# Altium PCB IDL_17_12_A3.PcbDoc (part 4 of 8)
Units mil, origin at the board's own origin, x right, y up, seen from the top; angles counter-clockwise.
Board outline 5119.97 x 10350 mil, 6 copper layers (Top Signal, 3.3 Volt, GND, 5 Volt, Split Plane, Bot Signal), stack 66.2 mil thick; 510 components, 178 nets, 2317 pads, 385 vias.
Unrouted connection lines stored in the file: 1.
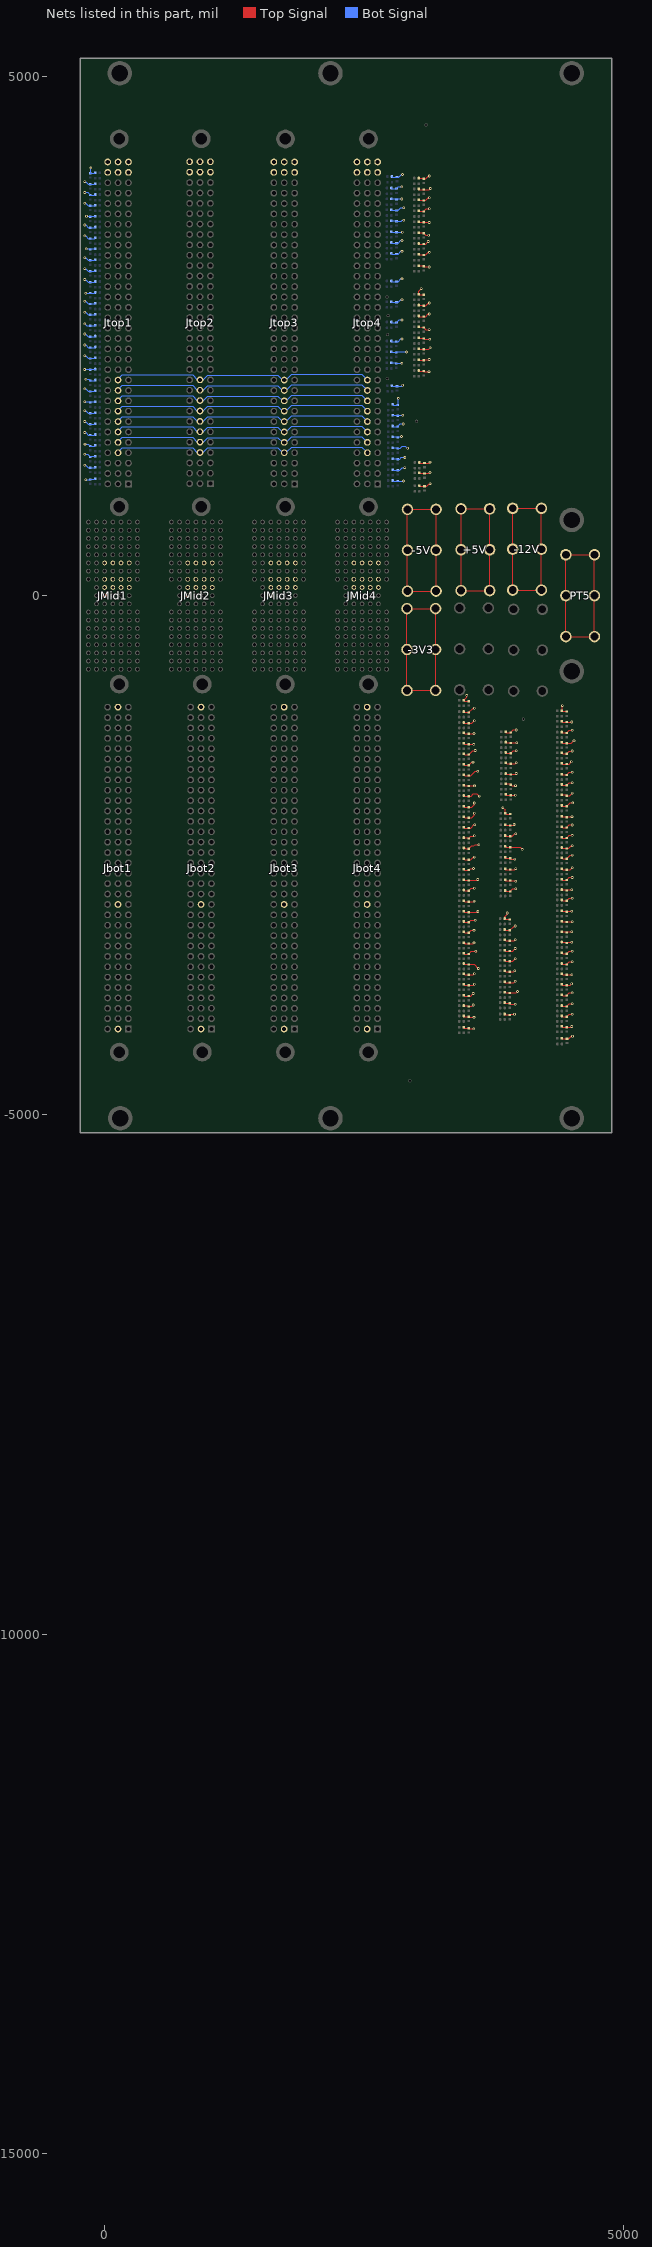
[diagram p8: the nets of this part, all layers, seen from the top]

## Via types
v1: diameter 25.59, hole 11.81, Top Signal to Bot Signal, 385 vias

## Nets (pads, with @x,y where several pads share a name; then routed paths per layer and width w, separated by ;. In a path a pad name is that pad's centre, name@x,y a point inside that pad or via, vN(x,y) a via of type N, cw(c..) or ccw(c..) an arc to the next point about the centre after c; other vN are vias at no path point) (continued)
5V: +5V.1 +5V.2 +5V.3 +5V.4 +5V.5 +5V.6 CR_IDL_17_12_TerA1.2 CR_IDL_17_12_TerA2.2 CR_IDL_17_12_TerA3.2 CR_IDL_17_12_TerA4.2 CR_IDL_17_12_TerA5.2 CR_IDL_17_12_TerA6.2 CR_IDL_17_12_TerA7.2 CR_IDL_17_12_TerA8.2 CR_IDL_17_12_TerA9.2 CR_IDL_17_12_TerA10.2 CR_IDL_17_12_TerA11.2 CR_IDL_17_12_TerA12.2 CR_IDL_17_12_TerA13.2 CR_IDL_17_12_TerA14.2 CR_IDL_17_12_TerA15.2 CR_IDL_17_12_TerA16.2 CR_IDL_17_12_TerA17.2 CR_IDL_17_12_TerA18.2 CR_IDL_17_12_TerA19.2 CR_IDL_17_12_TerA20.2 CR_IDL_17_12_TerA21.2 CR_IDL_17_12_TerA22.2 CR_IDL_17_12_TerA23.2 CR_IDL_17_12_TerA24.2 CR_IDL_17_12_TerA25.2 CR_IDL_17_12_TerA26.2 CR_IDL_17_12_TerA27.2 CR_IDL_17_12_TerA28.2 CR_IDL_17_12_TerA29.2 CR_IDL_17_12_TerA30.2 CR_IDL_17_12_TerA31.2 CR_IDL_17_12_TerA32.2 CR_IDL_17_12_TerA33.2 CR_IDL_17_12_TerA34.2 CR_IDL_17_12_TerA35.2 CR_IDL_17_12_TerA36.2 CR_IDL_17_12_TerA37.2 CR_IDL_17_12_TerA38.2 CR_IDL_17_12_TerA39.2 CR_IDL_17_12_TerA40.2 CR_IDL_17_12_TerA41.2 CR_IDL_17_12_TerA42.2 CR_IDL_17_12_TerA43.2 CR_IDL_17_12_TerA44.2 CR_IDL_17_12_TerA45.2 CR_IDL_17_12_TerA46.2 CR_IDL_17_12_TerA47.2 CR_IDL_17_12_TerA48.2 CR_IDL_17_12_TerA49.2 CR_IDL_17_12_TerA50.2 CR_IDL_17_12_TerA51.2 CR_IDL_17_12_TerA52.2 CR_IDL_17_12_TerA53.2 CR_IDL_17_12_TerA54.2 CR_IDL_17_12_TerA55.2 CR_IDL_17_12_TerA56.2 CR_IDL_17_12_TerA57.2 CR_IDL_17_12_TerA58.2 CR_IDL_17_12_TerA59.2 CR_IDL_17_12_TerA60.2 CR_IDL_17_12_TerA61.2 CR_IDL_17_12_TerA62.2 CR_IDL_17_12_TerA63.2 CR_IDL_17_12_TerA64.2 CR_IDL_17_12_TerA65.2 CR_IDL_17_12_TerA66.2 CR_IDL_17_12_TerA67.2 CR_IDL_17_12_TerA68.2 CR_IDL_17_12_TerA69.2 CR_IDL_17_12_TerA70.2 CR_IDL_17_12_TerA71.2 CR_IDL_17_12_TerA72.2 CRB_IDL_17_12_TerB1.2 CRB_IDL_17_12_TerB2.2 CRB_IDL_17_12_TerB3.2 CRB_IDL_17_12_TerB4.2 CRB_IDL_17_12_TerB5.2 CRB_IDL_17_12_TerB6.2 CRB_IDL_17_12_TerB7.2 CRB_IDL_17_12_TerB8.2 CRB_IDL_17_12_TerB9.2 CRB_IDL_17_12_TerB10.2 CRB_IDL_17_12_TerB11.2 CRB_IDL_17_12_TerB12.2 CRB_IDL_17_12_TerB13.2 CRB_IDL_17_12_TerB14.2 CRB_IDL_17_12_TerB15.2 CRB_IDL_17_12_TerB16.2 CRB_IDL_17_12_TerB17.2 CRB_IDL_17_12_TerB18.2 CRB_IDL_17_12_TerB19.2 CRB_IDL_17_12_TerB20.2 CRB_IDL_17_12_TerB21.2 CRB_IDL_17_12_TerB22.2 CRB_IDL_17_12_TerB23.2 CRB_IDL_17_12_TerB24.2 CRB_IDL_17_12_TerB25.2 CRB_IDL_17_12_TerB26.2 CRB_IDL_17_12_TerB27.2 CRB_IDL_17_12_TerB28.2 CRB_IDL_17_12_TerB29.2 CRB_IDL_17_12_TerB30.2 CRB_IDL_17_12_TerB31.2 CRB_IDL_17_12_TerB32.2 CRB_IDL_17_12_TerB33.2 CRB_IDL_17_12_TerB34.2 CRB_IDL_17_12_TerB35.2 CRB_IDL_17_12_TerB36.2 CRB_IDL_17_12_TerB37.2 CRB_IDL_17_12_TerB38.2 CRB_IDL_17_12_TerB39.2 CRB_IDL_17_12_TerB40.2 CRB_IDL_17_12_TerB41.2 CRB_IDL_17_12_TerB42.2 CRB_IDL_17_12_TerB43.2 CRB_IDL_17_12_TerB44.2 CRB_IDL_17_12_TerB45.2 CRB_IDL_17_12_TerB46.2 CRB_IDL_17_12_TerB47.2 CRB_IDL_17_12_TerB48.2 CRB_IDL_17_12_TerB49.2 CRB_IDL_17_12_TerB50.2 CRB_IDL_17_12_TerB51.2 CRB_IDL_17_12_TerB52.2 CRB_IDL_17_12_TerB53.2 CRB_IDL_17_12_TerB54.2 CRB_IDL_17_12_TerB55.2 CRB_IDL_17_12_TerB56.2 CRB_IDL_17_12_TerB57.2 CRB_IDL_17_12_TerB58.2 CRB_IDL_17_12_TerB59.2 CRB_IDL_17_12_TerB60.2 CRB_IDL_17_12_TerB61.2 CRB_IDL_17_12_TerB62.2 CRB_IDL_17_12_TerB63.2 CRB_IDL_17_12_TerB64.2 CRB_IDL_17_12_TerB65.2 CRB_IDL_17_12_TerB66.2 CRB_IDL_17_12_TerB67.2 CRB_IDL_17_12_TerB68.2 CRB_IDL_17_12_TerB69.2 CRB_IDL_17_12_TerB70.2 CRB_IDL_17_12_TerB71.2 CRB_IDL_17_12_TerB72.2 CRB_IDL_17_12_TerB73.2 CRB_IDL_17_12_TerB74.2 CRB_IDL_17_12_TerB75.2 CRB_IDL_17_12_TerB76.2 CRB_IDL_17_12_TerB77.2 CRB_IDL_17_12_TerB78.2 CRB_IDL_17_12_TerB79.2 CRB_IDL_17_12_TerB80.2 CRB_IDL_17_12_TerB81.2 CRB_IDL_17_12_TerB82.2 CRB_IDL_17_12_TerB83.2 CRB_IDL_17_12_TerB84.2 CRB_IDL_17_12_TerB85.2 CRB_IDL_17_12_TerB86.2 CRB_IDL_17_12_TerB87.2 CRB_IDL_17_12_TerB88.2 CRB_IDL_17_12_TerB89.2 Jbot1.B1 Jbot1.B13 Jbot1.B32 Jbot2.B1 Jbot2.B13 Jbot2.B32 Jbot3.B1 Jbot3.B13 Jbot3.B32 Jbot4.B1 Jbot4.B13 Jbot4.B32 Jtop1.A32 Jtop1.B31 Jtop1.B32 Jtop1.C32 Jtop2.A32 Jtop2.B31 Jtop2.B32 Jtop2.C32 Jtop3.A32 Jtop3.B31 Jtop3.B32 Jtop3.C32 Jtop4.A32 Jtop4.B31 Jtop4.B32 Jtop4.C32 R1R_IDL_17_12_TerA1.2 R1R_IDL_17_12_TerA2.2 R1R_IDL_17_12_TerA3.2 R1R_IDL_17_12_TerA4.2 R1R_IDL_17_12_TerA5.2 R1R_IDL_17_12_TerA6.2 R1R_IDL_17_12_TerA7.2 R1R_IDL_17_12_TerA8.2 R1R_IDL_17_12_TerA9.2 R1R_IDL_17_12_TerA10.2 R1R_IDL_17_12_TerA11.2 R1R_IDL_17_12_TerA12.2 R1R_IDL_17_12_TerA13.2 R1R_IDL_17_12_TerA14.2 R1R_IDL_17_12_TerA15.2 R1R_IDL_17_12_TerA16.2 R1R_IDL_17_12_TerA17.2 R1R_IDL_17_12_TerA18.2 R1R_IDL_17_12_TerA19.2 R1R_IDL_17_12_TerA20.2 R1R_IDL_17_12_TerA21.2 R1R_IDL_17_12_TerA22.2 R1R_IDL_17_12_TerA23.2 R1R_IDL_17_12_TerA24.2 R1R_IDL_17_12_TerA25.2 R1R_IDL_17_12_TerA26.2 R1R_IDL_17_12_TerA27.2 R1R_IDL_17_12_TerA28.2 R1R_IDL_17_12_TerA29.2 R1R_IDL_17_12_TerA30.2 R1R_IDL_17_12_TerA31.2 R1R_IDL_17_12_TerA32.2 R1R_IDL_17_12_TerA33.2 R1R_IDL_17_12_TerA34.2 R1R_IDL_17_12_TerA35.2 R1R_IDL_17_12_TerA36.2 R1R_IDL_17_12_TerA37.2 R1R_IDL_17_12_TerA38.2 R1R_IDL_17_12_TerA39.2 R1R_IDL_17_12_TerA40.2 R1R_IDL_17_12_TerA41.2 R1R_IDL_17_12_TerA42.2 R1R_IDL_17_12_TerA43.2 R1R_IDL_17_12_TerA44.2 R1R_IDL_17_12_TerA45.2 R1R_IDL_17_12_TerA46.2 R1R_IDL_17_12_TerA47.2 R1R_IDL_17_12_TerA48.2 R1R_IDL_17_12_TerA49.2 R1R_IDL_17_12_TerA50.2 R1R_IDL_17_12_TerA51.2 R1R_IDL_17_12_TerA52.2 R1R_IDL_17_12_TerA53.2 R1R_IDL_17_12_TerA54.2 R1R_IDL_17_12_TerA55.2 R1R_IDL_17_12_TerA56.2 R1R_IDL_17_12_TerA57.2 R1R_IDL_17_12_TerA58.2 R1R_IDL_17_12_TerA59.2 R1R_IDL_17_12_TerA60.2 R1R_IDL_17_12_TerA61.2 R1R_IDL_17_12_TerA62.2 R1R_IDL_17_12_TerA63.2 R1R_IDL_17_12_TerA64.2 R1R_IDL_17_12_TerA65.2 R1R_IDL_17_12_TerA66.2 R1R_IDL_17_12_TerA67.2 R1R_IDL_17_12_TerA68.2 R1R_IDL_17_12_TerA69.2 R1R_IDL_17_12_TerA70.2 R1R_IDL_17_12_TerA71.2 R1R_IDL_17_12_TerA72.2 R1RB_IDL_17_12_TerB1.2 R1RB_IDL_17_12_TerB2.2 R1RB_IDL_17_12_TerB3.2 R1RB_IDL_17_12_TerB4.2 R1RB_IDL_17_12_TerB5.2 R1RB_IDL_17_12_TerB6.2 R1RB_IDL_17_12_TerB7.2 R1RB_IDL_17_12_TerB8.2 R1RB_IDL_17_12_TerB9.2 R1RB_IDL_17_12_TerB10.2 R1RB_IDL_17_12_TerB11.2 R1RB_IDL_17_12_TerB12.2 R1RB_IDL_17_12_TerB13.2 R1RB_IDL_17_12_TerB14.2 R1RB_IDL_17_12_TerB15.2 R1RB_IDL_17_12_TerB16.2 R1RB_IDL_17_12_TerB17.2 R1RB_IDL_17_12_TerB18.2 R1RB_IDL_17_12_TerB19.2 R1RB_IDL_17_12_TerB20.2 R1RB_IDL_17_12_TerB21.2 R1RB_IDL_17_12_TerB22.2 R1RB_IDL_17_12_TerB23.2 R1RB_IDL_17_12_TerB24.2 R1RB_IDL_17_12_TerB25.2 R1RB_IDL_17_12_TerB26.2 R1RB_IDL_17_12_TerB27.2 R1RB_IDL_17_12_TerB28.2 R1RB_IDL_17_12_TerB29.2 R1RB_IDL_17_12_TerB30.2 R1RB_IDL_17_12_TerB31.2 R1RB_IDL_17_12_TerB32.2 R1RB_IDL_17_12_TerB33.2 R1RB_IDL_17_12_TerB34.2 R1RB_IDL_17_12_TerB35.2 R1RB_IDL_17_12_TerB36.2 R1RB_IDL_17_12_TerB37.2 R1RB_IDL_17_12_TerB38.2 R1RB_IDL_17_12_TerB39.2 R1RB_IDL_17_12_TerB40.2 R1RB_IDL_17_12_TerB41.2 R1RB_IDL_17_12_TerB42.2 R1RB_IDL_17_12_TerB43.2 R1RB_IDL_17_12_TerB44.2 R1RB_IDL_17_12_TerB45.2 R1RB_IDL_17_12_TerB46.2 R1RB_IDL_17_12_TerB47.2 R1RB_IDL_17_12_TerB48.2 R1RB_IDL_17_12_TerB49.2 R1RB_IDL_17_12_TerB50.2 R1RB_IDL_17_12_TerB51.2 R1RB_IDL_17_12_TerB52.2 R1RB_IDL_17_12_TerB53.2 R1RB_IDL_17_12_TerB54.2 R1RB_IDL_17_12_TerB55.2 R1RB_IDL_17_12_TerB56.2 R1RB_IDL_17_12_TerB57.2 R1RB_IDL_17_12_TerB58.2 R1RB_IDL_17_12_TerB59.2 R1RB_IDL_17_12_TerB60.2 R1RB_IDL_17_12_TerB61.2 R1RB_IDL_17_12_TerB62.2 R1RB_IDL_17_12_TerB63.2 R1RB_IDL_17_12_TerB64.2 R1RB_IDL_17_12_TerB65.2 R1RB_IDL_17_12_TerB66.2 R1RB_IDL_17_12_TerB67.2 R1RB_IDL_17_12_TerB68.2 R1RB_IDL_17_12_TerB69.2 R1RB_IDL_17_12_TerB70.2 R1RB_IDL_17_12_TerB71.2 R1RB_IDL_17_12_TerB72.2 R1RB_IDL_17_12_TerB73.2 R1RB_IDL_17_12_TerB74.2 R1RB_IDL_17_12_TerB75.2 R1RB_IDL_17_12_TerB76.2 R1RB_IDL_17_12_TerB77.2 R1RB_IDL_17_12_TerB78.2 R1RB_IDL_17_12_TerB79.2 R1RB_IDL_17_12_TerB80.2 R1RB_IDL_17_12_TerB81.2 R1RB_IDL_17_12_TerB82.2 R1RB_IDL_17_12_TerB83.2 R1RB_IDL_17_12_TerB84.2 R1RB_IDL_17_12_TerB85.2 R1RB_IDL_17_12_TerB86.2 R1RB_IDL_17_12_TerB87.2 R1RB_IDL_17_12_TerB88.2 R1RB_IDL_17_12_TerB89.2 | length 18453.1
  Top Signal w8: Jtop4.A32@2628.72,4176.52 Jtop4.A32@2628.72,4182.06 ; R1R_IDL_17_12_TerA40.2@3024.42,2168.36 3030.32,2162.46 CR_IDL_17_12_TerA40.2@3073.37,2162.46 ; R1R_IDL_17_12_TerA39.2@3024.42,2273.36 3030.32,2267.46 CR_IDL_17_12_TerA39.2@3073.37,2267.46 3079.93,2274.01 v1(3124.74,2274.01) ; R1R_IDL_17_12_TerA38.2@3024.42,2378.36 3030.32,2372.46 CR_IDL_17_12_TerA38.2@3073.37,2372.46 3120.11,2372.46 v1(3133.9,2386.25) ; R1R_IDL_17_12_TerA37.2@3024.42,2483.36 3030.32,2477.46 CR_IDL_17_12_TerA37.2@3073.37,2477.46 3081.48,2469.35 v1(3130.24,2469.35) ; R1R_IDL_17_12_TerA36.2@3024.42,2588.36 3052.71,2582.46 CR_IDL_17_12_TerA36.2@3073.37,2582.46 3093.89,2561.94 v1(3124.64,2561.94) ; R1R_IDL_17_12_TerA35.2@3024.42,2693.36 3030.32,2687.46 CR_IDL_17_12_TerA35.2@3073.37,2687.46 3091.71,2687.46 3117.04,2712.79 v1(3126.89,2712.79) ; R1R_IDL_17_12_TerA34.2@3024.42,2798.36 3067.47,2798.36 CR_IDL_17_12_TerA34.2@3073.37,2792.46 3091.71,2792.46 3117.04,2817.79 v1(3126.89,2817.79) ; R1R_IDL_17_12_TerA32.2@3024.42,3178.36 3067.47,3178.36 CR_IDL_17_12_TerA32.2@3073.37,3172.46 3080.79,3165.04 v1(3125.26,3165.04) ; R1R_IDL_17_12_TerA31.2@3024.42,3286.36 3030.32,3280.46 CR_IDL_17_12_TerA31.2@3073.37,3280.46 3091.71,3280.46 3117.04,3305.79 v1(3126.89,3305.79) ; R1R_IDL_17_12_TerA30.2@3024.42,3391.36 3030.32,3385.46 CR_IDL_17_12_TerA30.2@3073.37,3385.46 3091.71,3385.46 v1(3117.04,3410.79) ; R1R_IDL_17_12_TerA29.2@3024.42,3496.36 3067.47,3496.36 CR_IDL_17_12_TerA29.2@3073.37,3490.46 3093.56,3470.27 v1(3119.45,3470.27) ; R1R_IDL_17_12_TerA28.2@3024.42,3601.36 3030.32,3595.46 CR_IDL_17_12_TerA28.2@3073.37,3595.46 3123.44,3595.46 v1(3126.01,3592.88) ; R1R_IDL_17_12_TerA27.2@3024.42,3706.36 3030.32,3700.46 CR_IDL_17_12_TerA27.2@3073.37,3700.46 3098.7,3725.79 v1(3126.89,3725.79) ; R1R_IDL_17_12_TerA26.2@3024.42,3811.36 3030.32,3805.46 CR_IDL_17_12_TerA26.2@3073.37,3805.46 3091.71,3805.46 3117.04,3830.79 v1(3126.89,3830.79) ; R1R_IDL_17_12_TerA25.2@3024.42,3916.36 3030.32,3910.46 CR_IDL_17_12_TerA25.2@3073.37,3910.46 CR_IDL_17_12_TerA25.2@3074.84,3910.46 ; R1R_IDL_17_12_TerA24.2@3024.42,4021.36 3067.47,4021.36 CR_IDL_17_12_TerA24.2@3073.37,4015.46 3091.71,4015.46 3117.04,4040.79 v1(3126.89,4040.79) ; R1R_IDL_17_12_TerA43.2@3030.24,1053.96 CR_IDL_17_12_TerA43.2@3079.2,1053.96 3100.74,1053.96 3125.86,1079.08 v1(3133.78,1079.08) ; R1R_IDL_17_12_TerA42.2@3030.32,1182.84 3036.22,1176.93 CR_IDL_17_12_TerA42.2@3079.27,1176.93 3123.46,1176.93 v1(3132.79,1186.26) ; R1R_IDL_17_12_TerA41.2@3030.32,1276.93 CR_IDL_17_12_TerA41.2@3079.27,1276.93 3123.46,1276.93 v1(3132.79,1286.26) ; v1(3048.76,2956.88) 3024.42,2932.54 R1R_IDL_17_12_TerA33.2@3024.42,2903.36 3030.32,2897.46 CR_IDL_17_12_TerA33.2@3073.37,2897.46 ; CR_IDL_17_12_TerA25.2@3073.11,3908.73 CR_IDL_17_12_TerA25.2@3074.84,3910.46 ; CR_IDL_17_12_TerA40.2@3073.37,2157.75 v1(3123.09,2157.75) ; v1(3136.58,3921.34) 3125.69,3910.46 CR_IDL_17_12_TerA25.2@3074.84,3910.46 ; R1RB_IDL_17_12_TerB31.2@3457.78,-4047.31 3457.78,-4055.81 CRB_IDL_17_12_TerB31.2@3506.6,-4055.81 3512.11,-4061.32 v1(3556.4,-4061.32) ; R1RB_IDL_17_12_TerB30.2@3457.78,-3947.31 3498.1,-3947.31 CRB_IDL_17_12_TerB30.2@3506.6,-3955.81 3535.75,-3955.81 v1(3549.99,-3941.58) ; R1RB_IDL_17_12_TerB29.2@3457.78,-3847.31 3466.29,-3855.81 CRB_IDL_17_12_TerB29.2@3506.6,-3855.81 3524.94,-3855.81 v1(3550.27,-3830.48) ; R1RB_IDL_17_12_TerB28.2@3457.78,-3742.31 3466.29,-3750.81 CRB_IDL_17_12_TerB28.2@3506.6,-3750.81 3550.79,-3750.81 v1(3560.12,-3741.48) ; R1RB_IDL_17_12_TerB27.2@3457.78,-3642.31 3466.29,-3650.81 CRB_IDL_17_12_TerB27.2@3506.6,-3650.81 3550.79,-3650.81 v1(3560.12,-3641.48) ; R1RB_IDL_17_12_TerB26.2@3457.78,-3542.31 3466.29,-3550.81 CRB_IDL_17_12_TerB26.2@3506.6,-3550.81 ; R1RB_IDL_17_12_TerB25.2@3457.78,-3442.31 3466.29,-3450.81 CRB_IDL_17_12_TerB25.2@3506.6,-3450.81 3532.34,-3425.08 v1(3574.01,-3425.08) 3579.11,-3425.08 3582.06,-3428.02 v1@3574.01,-3428.02 ; R1RB_IDL_17_12_TerB23.2@3457.78,-3237.31 3466.29,-3245.81 CRB_IDL_17_12_TerB23.2@3506.6,-3245.81 3529,-3223.41 v1(3557.19,-3223.41) ; R1RB_IDL_17_12_TerB22.2@3457.78,-3137.31 3466.29,-3145.81 CRB_IDL_17_12_TerB22.2@3506.6,-3145.81 3525.99,-3126.43 v1(3569.38,-3126.43) ; R1RB_IDL_17_12_TerB21.2@3457.78,-3039.31 3466.29,-3047.81 CRB_IDL_17_12_TerB21.2@3506.6,-3047.81 3588.51,-3047.81 v1(3594.38,-3041.94) ; R1RB_IDL_17_12_TerB20.2@3457.78,-2939.31 3466.29,-2947.81 CRB_IDL_17_12_TerB20.2@3506.6,-2947.81 3551.14,-2947.81 v1(3557.68,-2941.28) ; R1RB_IDL_17_12_TerB19.2@3457.78,-2834.31 3466.29,-2842.81 CRB_IDL_17_12_TerB19.2@3506.6,-2842.81 3531.93,-2817.48 v1(3560.12,-2817.48) ; R1RB_IDL_17_12_TerB18.2@3457.78,-2734.31 3466.29,-2742.81 CRB_IDL_17_12_TerB18.2@3506.6,-2742.81 3582.79,-2742.81 v1(3592.12,-2733.48) ; R1RB_IDL_17_12_TerB17.2@3457.78,-2634.31 3466.29,-2642.81 CRB_IDL_17_12_TerB17.2@3506.6,-2642.81 3521.78,-2627.63 v1(3551.65,-2627.63) ; R1RB_IDL_17_12_TerB16.2@3457.78,-2534.31 3466.29,-2542.81 CRB_IDL_17_12_TerB16.2@3506.6,-2542.81 3524.94,-2542.81 3550.27,-2517.48 v1(3560.12,-2517.48) ; R1RB_IDL_17_12_TerB15.2@3457.78,-2429.31 3469,-2429.31 3477.5,-2437.81 CRB_IDL_17_12_TerB15.2@3506.6,-2437.81 3534.91,-2409.51 3554.87,-2409.51 3566.41,-2397.97 v1(3603.72,-2397.97) ; R1RB_IDL_17_12_TerB14.2@3457.78,-2329.31 3498.1,-2329.31 CRB_IDL_17_12_TerB14.2@3506.6,-2337.81 3525.45,-2318.96 3553.64,-2318.96 v1(3560.12,-2312.48) ; R1RB_IDL_17_12_TerB13.2@3457.78,-2229.31 3466.29,-2237.81 CRB_IDL_17_12_TerB13.2@3506.6,-2237.81 3524.94,-2237.81 3560.12,-2202.63 3563.45,-2205.96 v1(3564.24,-2205.96) ; R1RB_IDL_17_12_TerB12.2@3457.78,-2129.31 3466.29,-2137.81 CRB_IDL_17_12_TerB12.2@3506.6,-2137.81 3534.79,-2137.81 3560.12,-2112.48 v1(3560.12,-2096.48) ; R1RB_IDL_17_12_TerB11.2@3457.78,-2029.31 3466.29,-2037.81 CRB_IDL_17_12_TerB11.2@3506.6,-2037.81 3534.79,-2037.81 3560.12,-2012.48 v1(3560.12,-1996.48) ; R1RB_IDL_17_12_TerB10.2@3457.78,-1924.31 3466.29,-1932.81 CRB_IDL_17_12_TerB10.2@3506.6,-1932.81 3527.88,-1932.81 3550.68,-1910.02 3583.33,-1910.02 v1@3606.12,-1932.81 ; R1RB_IDL_17_12_TerB9.2@3457.78,-1824.31 3466.29,-1832.81 CRB_IDL_17_12_TerB9.2@3506.6,-1832.81 3559.96,-1832.81 v1(3560.95,-1831.82) ; R1RB_IDL_17_12_TerB8.2@3457.78,-1724.31 3466.29,-1732.81 CRB_IDL_17_12_TerB8.2@3506.6,-1732.81 3527.31,-1732.81 3568.64,-1691.48 v1(3592.12,-1691.48) ; R1RB_IDL_17_12_TerB7.2@3457.78,-1624.31 3466.29,-1632.81 CRB_IDL_17_12_TerB7.2@3506.6,-1632.81 3536.29,-1603.13 v1(3546.97,-1603.13) ; R1RB_IDL_17_12_TerB6.2@3457.78,-1521.31 3466.29,-1529.81 CRB_IDL_17_12_TerB6.2@3506.6,-1529.81 3544.9,-1491.52 v1(3569.4,-1491.52) ; R1RB_IDL_17_12_TerB5.2@3457.78,-1421.31 3466.29,-1429.81 CRB_IDL_17_12_TerB5.2@3506.6,-1429.81 v1@3553.65,-1429.81 ; R1RB_IDL_17_12_TerB4.2@3457.78,-1321.31 3466.29,-1329.81 CRB_IDL_17_12_TerB4.2@3506.6,-1329.81 v1@3556.23,-1329.81 ; R1RB_IDL_17_12_TerB3.2@3457.78,-1221.31 3466.29,-1229.81 CRB_IDL_17_12_TerB3.2@3506.6,-1229.81 3534.79,-1229.81 v1(3560.12,-1204.48) ; R1RB_IDL_17_12_TerB2.2@3457.78,-1116.31 3466.29,-1124.81 CRB_IDL_17_12_TerB2.2@3506.6,-1124.81 3547.93,-1083.48 v1(3560.12,-1083.48) ; R1RB_IDL_17_12_TerB32.2@3457.87,-4164.87 CRB_IDL_17_12_TerB32.2@3506.2,-4164.87 3513.39,-4172.06 v1(3554.44,-4172.06) ; v1(3487.68,-960.63) 3486.47,-960.63 3486.47,-979.46 R1RB_IDL_17_12_TerB1.2@3457.09,-1008.84 3465.59,-1017.34 CRB_IDL_17_12_TerB1.2@3505.91,-1017.34 ; CRB_IDL_17_12_TerB26.2@3506.59,-3550.24 3514.6,-3550.08 3558.63,-3550.08 v1(3598.99,-3590.44) ; v1@3560.44,-3344.08 v1(3556.33,-3344.08) 3549.59,-3350.81 CRB_IDL_17_12_TerB24.2@3506.6,-3350.81 3477.5,-3350.81 ; v1(3835.08,-2041.02) 3856.73,-2062.68 R1RB_IDL_17_12_TerB40.2@3856.73,-2094.54 3865.24,-2103.05 CRB_IDL_17_12_TerB40.2@3905.55,-2103.05 ; R1RB_IDL_17_12_TerB57.2@3847.52,-4037.02 CRB_IDL_17_12_TerB57.2@3900.51,-4037.02 3907.21,-4030.33 v1(3946.67,-4030.33) ; R1RB_IDL_17_12_TerB56.2@3851.73,-3917.54 3851.73,-3926.05 CRB_IDL_17_12_TerB56.2@3900.55,-3926.05 3908.32,-3933.81 v1(3953.35,-3933.81) ; R1RB_IDL_17_12_TerB55.2@3851.73,-3817.54 3860.24,-3826.05 CRB_IDL_17_12_TerB55.2@3900.55,-3826.05 3961.69,-3826.05 v1(3975.74,-3812) ; R1RB_IDL_17_12_TerB54.2@3851.73,-3717.54 3851.73,-3726.05 CRB_IDL_17_12_TerB54.2@3900.55,-3726.05 3939.37,-3726.05 v1(3952.88,-3712.54) ; R1RB_IDL_17_12_TerB53.2@3851.73,-3612.54 3860.24,-3621.05 CRB_IDL_17_12_TerB53.2@3900.55,-3621.05 3939.18,-3621.05 ; R1RB_IDL_17_12_TerB52.2@3851.73,-3512.54 3860.24,-3521.05 CRB_IDL_17_12_TerB52.2@3900.55,-3521.05 3928.74,-3521.05 v1(3954.07,-3495.72) ; R1RB_IDL_17_12_TerB51.2@3851.73,-3414.54 3860.24,-3423.05 CRB_IDL_17_12_TerB51.2@3900.55,-3423.05 3928.74,-3423.05 v1(3954.07,-3397.72) ; R1RB_IDL_17_12_TerB50.2@3851.73,-3314.54 3860.24,-3323.05 CRB_IDL_17_12_TerB50.2@3900.55,-3323.05 3944.74,-3323.05 v1(3954.07,-3313.72) ; R1RB_IDL_17_12_TerB49.2@3852.45,-3223.05 CRB_IDL_17_12_TerB49.2@3900.55,-3223.05 3941.88,-3181.72 v1(3954.07,-3181.72) ; R1RB_IDL_17_12_TerB47.2@3854.98,-2848.05 CRB_IDL_17_12_TerB47.2@3905.55,-2848.05 3930.88,-2822.72 v1(3959.07,-2822.72) ; R1RB_IDL_17_12_TerB46.2@3856.66,-2743.05 CRB_IDL_17_12_TerB46.2@3905.55,-2743.05 3952.4,-2743.05 v1(3959.07,-2749.72) ; R1RB_IDL_17_12_TerB44.2@3856.73,-2519.54 3856.73,-2528.05 CRB_IDL_17_12_TerB44.2@3905.55,-2528.05 3914.52,-2537.01 v1(3948.08,-2537.01) ; R1RB_IDL_17_12_TerB43.2@3856.73,-2414.54 3865.24,-2423.05 CRB_IDL_17_12_TerB43.2@3905.55,-2423.05 4000.4,-2423.05 v1(4021.07,-2443.72) ; R1RB_IDL_17_12_TerB42.2@3856.73,-2309.54 3865.24,-2318.05 CRB_IDL_17_12_TerB42.2@3905.55,-2318.05 3923.89,-2318.05 3949.22,-2292.72 v1(3959.07,-2292.72) ; R1RB_IDL_17_12_TerB41.2@3856.76,-2213.05 CRB_IDL_17_12_TerB41.2@3905.55,-2213.05 3933.74,-2213.05 v1(3943.07,-2203.72) ; R1RB_IDL_17_12_TerB45.2@3858.06,-2638.05 CRB_IDL_17_12_TerB45.2@3905.55,-2638.05 3949.74,-2638.05 v1(3959.07,-2628.72) ; R1RB_IDL_17_12_TerB39.2@3861.73,-1912.89 3861.73,-1921.39 CRB_IDL_17_12_TerB39.2@3910.55,-1921.39 v1@3955.44,-1921.39 ; R1RB_IDL_17_12_TerB38.2@3861.73,-1812.89 3902.05,-1812.89 CRB_IDL_17_12_TerB38.2@3910.55,-1821.39 3918.34,-1829.18 v1(3955.89,-1829.18) ; R1RB_IDL_17_12_TerB37.2@3861.73,-1712.89 3870.24,-1721.39 CRB_IDL_17_12_TerB37.2@3910.55,-1721.39 3954.74,-1721.39 v1(3964.07,-1712.06) ; R1RB_IDL_17_12_TerB36.2@3861.73,-1609.89 3870.24,-1618.39 CRB_IDL_17_12_TerB36.2@3910.55,-1618.39 3953.59,-1618.39 v1(3962.92,-1609.06) ; R1RB_IDL_17_12_TerB35.2@3861.73,-1509.89 3870.24,-1518.39 CRB_IDL_17_12_TerB35.2@3910.55,-1518.39 3935.88,-1493.06 v1(3964.07,-1493.06) ; R1RB_IDL_17_12_TerB34.2@3861.73,-1409.89 3870.24,-1418.39 CRB_IDL_17_12_TerB34.2@3910.55,-1418.39 v1@3968.21,-1418.39 ; R1RB_IDL_17_12_TerB33.2@3863.95,-1318.39 CRB_IDL_17_12_TerB33.2@3910.55,-1318.39 3935.88,-1293.06 v1(3964.07,-1293.06) ; v1(3876.08,-3056.02) 3876.08,-3066.37 3851.73,-3090.71 R1RB_IDL_17_12_TerB48.2@3851.73,-3109.54 3860.24,-3118.05 CRB_IDL_17_12_TerB48.2@3900.55,-3118.05 ; R1RB_IDL_17_12_TerB88.2@4401.47,-4147.25 4409.97,-4155.75 CRB_IDL_17_12_TerB88.2@4450.29,-4155.75 4491.11,-4155.75 v1(4498.65,-4148.21) ; R1RB_IDL_17_12_TerB87.2@4401.47,-4047.25 4409.97,-4055.75 CRB_IDL_17_12_TerB87.2@4450.29,-4055.75 4475.62,-4030.42 v1(4503.81,-4030.42) ; R1RB_IDL_17_12_TerB86.2@4401.47,-3947.25 4409.97,-3955.75 CRB_IDL_17_12_TerB86.2@4450.29,-3955.75 4475.62,-3930.42 v1(4503.81,-3930.42) ; R1RB_IDL_17_12_TerB85.2@4401.47,-3842.25 4409.97,-3850.75 CRB_IDL_17_12_TerB85.2@4450.29,-3850.75 4475.62,-3825.42 v1(4503.81,-3825.42) ; R1RB_IDL_17_12_TerB84.2@4401.47,-3742.25 4409.97,-3750.75 CRB_IDL_17_12_TerB84.2@4450.29,-3750.75 4483.81,-3750.75 v1(4496.45,-3738.11) ; R1RB_IDL_17_12_TerB83.2@4401.47,-3642.25 4402.47,-3641.25 4411.39,-3650.17 v1(4499.28,-3650.17) ; R1RB_IDL_17_12_TerB82.2@4401.47,-3542.25 4409.97,-3550.75 CRB_IDL_17_12_TerB82.2@4450.29,-3550.75 4475.62,-3525.42 v1(4503.81,-3525.42) ; R1RB_IDL_17_12_TerB81.2@4401.47,-3440.25 4409.97,-3448.75 CRB_IDL_17_12_TerB81.2@4450.29,-3448.75 4475.62,-3423.42 v1(4503.81,-3423.42) ; R1RB_IDL_17_12_TerB80.2@4401.47,-3335.25 4404.19,-3337.97 v1(4498.45,-3337.97) ; R1RB_IDL_17_12_TerB79.2@4401.47,-3235.25 4402.54,-3236.32 v1(4497.78,-3236.32) ; R1RB_IDL_17_12_TerB78.2@4401.47,-3135.25 4406.56,-3140.34 CRB_IDL_17_12_TerB78.2@4450.29,-3140.34 ; R1RB_IDL_17_12_TerB77.2@4401.47,-3035.25 4404.48,-3038.27 v1(4498.52,-3038.27) ; R1RB_IDL_17_12_TerB76.2@4401.47,-2930.25 4409.97,-2938.75 CRB_IDL_17_12_TerB76.2@4450.29,-2938.75 4475.62,-2913.42 v1(4503.81,-2913.42) ; R1RB_IDL_17_12_TerB75.2@4401.47,-2830.25 4403.4,-2832.18 v1(4497.12,-2832.18) ; R1RB_IDL_17_12_TerB74.2@4401.47,-2730.25 4409.97,-2738.75 CRB_IDL_17_12_TerB74.2@4450.29,-2738.75 4475.62,-2713.42 v1(4503.81,-2713.42) ; R1RB_IDL_17_12_TerB73.2@4401.47,-2630.25 4409.97,-2638.75 CRB_IDL_17_12_TerB73.2@4450.29,-2638.75 4483.92,-2638.75 v1(4502.24,-2620.43) ; R1RB_IDL_17_12_TerB72.2@4401.47,-2525.25 4409.97,-2533.75 CRB_IDL_17_12_TerB72.2@4450.29,-2533.75 4485.47,-2498.56 v1(4503.81,-2498.56) ; R1RB_IDL_17_12_TerB71.2@4401.47,-2425.25 4409.97,-2433.75 CRB_IDL_17_12_TerB71.2@4450.29,-2433.75 4468.62,-2433.75 4493.95,-2408.42 v1(4503.81,-2408.42) ; R1RB_IDL_17_12_TerB70.2@4401.47,-2325.25 4409.97,-2333.75 CRB_IDL_17_12_TerB70.2@4450.29,-2333.75 4475.62,-2308.42 v1(4503.81,-2308.42) ; R1RB_IDL_17_12_TerB69.2@4401.47,-2225.25 4409.97,-2233.75 CRB_IDL_17_12_TerB69.2@4450.29,-2233.75 4475.62,-2208.42 v1(4503.81,-2208.42) ; R1RB_IDL_17_12_TerB68.2@4401.47,-2125.25 4403.97,-2127.76 CRB_IDL_17_12_TerB68.2@4450.29,-2127.76 ; R1RB_IDL_17_12_TerB67.2@4401.47,-2020.25 4409.97,-2028.75 CRB_IDL_17_12_TerB67.2@4450.29,-2028.75 4483.32,-1995.71 v1(4506.08,-1995.71) ; R1RB_IDL_17_12_TerB66.2@4401.47,-1918.25 4441.78,-1918.25 CRB_IDL_17_12_TerB66.2@4450.29,-1926.75 4478.48,-1926.75 v1(4503.81,-1901.42) ; R1RB_IDL_17_12_TerB65.2@4401.47,-1818.25 4409.97,-1826.75 CRB_IDL_17_12_TerB65.2@4450.29,-1826.75 4475.62,-1801.42 v1(4503.81,-1801.42) ; R1RB_IDL_17_12_TerB64.2@4401.47,-1718.25 4409.97,-1726.75 CRB_IDL_17_12_TerB64.2@4450.29,-1726.75 4475.62,-1701.42 v1(4503.81,-1701.42) ; R1RB_IDL_17_12_TerB63.2@4401.47,-1613.25 4409.97,-1621.75 CRB_IDL_17_12_TerB63.2@4450.29,-1621.75 4471.57,-1621.75 v1(4494.36,-1598.96) ; R1RB_IDL_17_12_TerB62.2@4401.47,-1513.25 4409.97,-1521.75 CRB_IDL_17_12_TerB62.2@4450.29,-1521.75 4475.62,-1496.42 v1(4503.81,-1496.42) ; R1RB_IDL_17_12_TerB61.2@4401.47,-1413.25 4409.97,-1421.75 CRB_IDL_17_12_TerB61.2@4450.29,-1421.75 4491.27,-1421.75 4516.6,-1396.42 v1(4519.81,-1396.42) ; R1RB_IDL_17_12_TerB60.2@4401.47,-1313.25 4409.97,-1321.75 CRB_IDL_17_12_TerB60.2@4450.29,-1321.75 4475.62,-1296.42 v1(4503.81,-1296.42) ; R1RB_IDL_17_12_TerB59.2@4401.47,-1208.25 4409.97,-1216.75 CRB_IDL_17_12_TerB59.2@4450.29,-1216.75 4498.05,-1216.75 v1(4498.56,-1217.26) ; R1RB_IDL_17_12_TerB58.2@4401.47,-1114.15 CRB_IDL_17_12_TerB58.2@4450.29,-1114.15 ; R1RB_IDL_17_12_TerB58.2@4401.47,-1108.25 4407.57,-1102.15 v1(4407.57,-1058.61) ; R1RB_IDL_17_12_TerB89.2@4403.41,-4262.25 4408.62,-4267.46 CRB_IDL_17_12_TerB89.2@4451.51,-4267.46 4469.85,-4267.46 4495.18,-4242.13 v1(4505.03,-4242.13) ; CRB_IDL_17_12_TerB78.2@4450.29,-3143.75 CRB_IDL_17_12_TerB78.2@4450.29,-3140.34 ; CRB_IDL_17_12_TerB68.2@4450.29,-2133.75 CRB_IDL_17_12_TerB68.2@4450.29,-2127.76 ; v1(4500.57,-2127.76) CRB_IDL_17_12_TerB68.2@4450.29,-2127.76 ; v1(4502.78,-3140.34) CRB_IDL_17_12_TerB78.2@4450.29,-3140.34 ; 3477.5,-3350.81 3466.29,-3350.81 R1RB_IDL_17_12_TerB24.2@3457.78,-3342.31 3469,-3342.31 3477.5,-3350.81
  Bot Signal w8: v1(-193.17,2178.31) -93.57,2178.31 R1R_IDL_17_12_TerA62.2@-89.92,2181.95 R1R_IDL_17_12_TerA62.2@-94.8,2181.95 ; v1(-192.4,1256.37) -182.55,1256.37 -157.22,1231.04 CR_IDL_17_12_TerA71.2@-138.88,1231.04 -95.83,1231.04 R1R_IDL_17_12_TerA71.2@-89.92,1236.95 ; v1(-192.4,1361.37) -164.21,1361.37 CR_IDL_17_12_TerA70.2@-138.88,1336.04 -132.97,1341.95 R1R_IDL_17_12_TerA70.2@-89.92,1341.95 ; v1(-192.4,1571.37) -182.55,1571.37 -157.22,1546.04 CR_IDL_17_12_TerA68.2@-138.88,1546.04 -95.83,1546.04 R1R_IDL_17_12_TerA68.2@-89.92,1551.95 ; v1(-192.4,1676.37) -182.55,1676.37 -157.22,1651.04 CR_IDL_17_12_TerA67.2@-138.88,1651.04 -95.83,1651.04 R1R_IDL_17_12_TerA67.2@-89.92,1656.95 ; v1(-192.4,1781.37) -182.55,1781.37 -157.22,1756.04 CR_IDL_17_12_TerA66.2@-138.88,1756.04 -95.83,1756.04 R1R_IDL_17_12_TerA66.2@-89.92,1761.95 ; v1(-192.4,1991.37) -182.55,1991.37 -157.22,1966.04 CR_IDL_17_12_TerA64.2@-138.88,1966.04 -95.83,1966.04 R1R_IDL_17_12_TerA64.2@-89.92,1971.95 ; v1(-192.4,2309.37) -182.55,2309.37 -157.22,2284.04 CR_IDL_17_12_TerA61.2@-138.88,2284.04 -95.83,2284.04 R1R_IDL_17_12_TerA61.2@-89.92,2289.95 ; v1(-192.4,2414.37) -182.55,2414.37 -157.22,2389.04 CR_IDL_17_12_TerA60.2@-138.88,2389.04 -95.83,2389.04 R1R_IDL_17_12_TerA60.2@-89.92,2394.95 ; v1(-192.4,2519.37) -182.55,2519.37 -157.22,2494.04 CR_IDL_17_12_TerA59.2@-138.88,2494.04 -95.83,2494.04 R1R_IDL_17_12_TerA59.2@-89.92,2499.95 ; v1(-192.4,2729.37) -182.55,2729.37 -157.22,2704.04 CR_IDL_17_12_TerA57.2@-138.88,2704.04 -95.83,2704.04 R1R_IDL_17_12_TerA57.2@-89.92,2709.95 ; v1(-192.4,2834.37) -182.55,2834.37 -157.22,2809.04 CR_IDL_17_12_TerA56.2@-138.88,2809.04 -95.83,2809.04 R1R_IDL_17_12_TerA56.2@-89.92,2814.95 ; v1(-192.4,3044.37) -182.55,3044.37 -157.22,3019.04 CR_IDL_17_12_TerA54.2@-138.88,3019.04 -95.83,3019.04 R1R_IDL_17_12_TerA54.2@-89.92,3024.95 ; v1(-192.4,3149.37) -182.55,3149.37 -157.22,3124.04 CR_IDL_17_12_TerA53.2@-138.88,3124.04 -95.83,3124.04 R1R_IDL_17_12_TerA53.2@-89.92,3129.95 ; v1(-192.4,3254.37) -182.55,3254.37 -157.22,3229.04 CR_IDL_17_12_TerA52.2@-138.88,3229.04 -95.83,3229.04 R1R_IDL_17_12_TerA52.2@-89.92,3234.95 ; v1(-192.4,3464.37) -182.55,3464.37 -157.22,3439.04 CR_IDL_17_12_TerA50.2@-138.88,3439.04 -95.83,3439.04 R1R_IDL_17_12_TerA50.2@-89.92,3444.95 ; v1(-192.4,3569.37) -182.55,3569.37 -157.22,3544.04 CR_IDL_17_12_TerA49.2@-138.88,3544.04 -95.83,3544.04 R1R_IDL_17_12_TerA49.2@-89.92,3549.95 ; v1(-192.4,3779.37) -182.55,3779.37 -157.22,3754.04 CR_IDL_17_12_TerA47.2@-138.88,3754.04 -95.83,3754.04 R1R_IDL_17_12_TerA47.2@-89.92,3759.95 ; v1(-192.4,3882.37) -164.21,3882.37 CR_IDL_17_12_TerA46.2@-138.88,3857.04 -95.83,3857.04 R1R_IDL_17_12_TerA46.2@-89.92,3862.95 ; v1(-192.4,3987.37) -182.55,3987.37 -157.22,3962.04 CR_IDL_17_12_TerA45.2@-138.88,3962.04 -95.83,3962.04 R1R_IDL_17_12_TerA45.2@-89.92,3967.95 ; v1(-191.54,2617.09) -173.5,2599.04 CR_IDL_17_12_TerA58.2@-138.88,2599.04 -95.83,2599.04 R1R_IDL_17_12_TerA58.2@-89.92,2604.95 R1R_IDL_17_12_TerA58.2@-94.94,2609.97 ; v1(-191.1,1867.52) -90.49,1867.52 R1R_IDL_17_12_TerA65.2@-89.92,1866.95 ; v1(-189.15,1459.24) -157.08,1459.24 CR_IDL_17_12_TerA69.2@-138.88,1441.04 -95.83,1441.04 R1R_IDL_17_12_TerA69.2@-89.92,1446.95 ; v1(-183.18,2912.68) -97.19,2912.68 R1R_IDL_17_12_TerA55.2@-89.92,2919.95 ; v1(-182.49,1117.17) -140.23,1117.17 -138.07,1115 CR_IDL_17_12_TerA72.2@-134.49,1118.58 ; v1(-180.88,2083.35) -178.12,2086.11 -153.95,2086.11 CR_IDL_17_12_TerA63.2@-138.88,2071.04 -95.83,2071.04 R1R_IDL_17_12_TerA63.2@-89.92,2076.95 ; v1(-178.11,3339.25) -90.62,3339.25 R1R_IDL_17_12_TerA51.2@-89.92,3339.95 ; v1(-175.47,3654.41) -92.19,3654.41 -90.78,3655.81 R1R_IDL_17_12_TerA48.2@-89.92,3654.95 ; CR_IDL_17_12_TerA72.2@-137.57,1118.58 CR_IDL_17_12_TerA72.2@-134.49,1118.58 ; v1(-132.66,4119.29) -132.66,4073.27 CR_IDL_17_12_TerA44.2@-138.88,4067.04 -95.83,4067.04 R1R_IDL_17_12_TerA44.2@-89.92,4072.95 ; R1R_IDL_17_12_TerA72.2@-89.94,1126.4 -97.75,1118.58 CR_IDL_17_12_TerA72.2@-134.49,1118.58 ; R1R_IDL_17_12_TerA14.2@2760.52,2242.47 2803.57,2242.47 CR_IDL_17_12_TerA14.2@2809.48,2236.56 2818.65,2236.56 2818.7,2236.61 v1(2862.35,2236.61) ; R1R_IDL_17_12_TerA12.2@2760.52,2452.47 2766.43,2446.56 CR_IDL_17_12_TerA12.2@2809.48,2446.56 2827.82,2446.56 2853.15,2471.89 v1(2863,2471.89) ; R1R_IDL_17_12_TerA11.2@2760.89,2635.68 2766.8,2629.77 CR_IDL_17_12_TerA11.2@2809.85,2629.77 2835.18,2655.1 v1(2863.37,2655.1) ; R1R_IDL_17_12_TerA10.2@2760.89,2830.68 2766.8,2824.77 CR_IDL_17_12_TerA10.2@2809.85,2824.77 2828.19,2824.77 2853.52,2850.1 v1(2863.37,2850.1) ; R1R_IDL_17_12_TerA9.2@2760.89,3030.68 2766.8,3024.77 CR_IDL_17_12_TerA9.2@2809.85,3024.77 2828.19,3024.77 2853.52,3050.1 v1(2863.37,3050.1) ; R1R_IDL_17_12_TerA8.2@2760.89,3295.68 2766.8,3289.77 CR_IDL_17_12_TerA8.2@2809.85,3289.77 2828.19,3289.77 2853.52,3315.1 v1(2863.37,3315.1) ; R1R_IDL_17_12_TerA7.2@2760.89,3400.68 2766.8,3394.77 CR_IDL_17_12_TerA7.2@2809.85,3394.77 2828.19,3394.77 2853.52,3420.1 v1(2863.37,3420.1) ; R1R_IDL_17_12_TerA6.2@2760.89,3506.52 2767.63,3499.77 CR_IDL_17_12_TerA6.2@2809.85,3499.77 ; R1R_IDL_17_12_TerA5.2@2760.89,3610.68 2803.94,3610.68 CR_IDL_17_12_TerA5.2@2809.85,3604.77 2854.04,3604.77 2863.37,3614.1 v1(2879.37,3614.1) ; R1R_IDL_17_12_TerA4.2@2760.89,3715.68 2766.8,3709.77 CR_IDL_17_12_TerA4.2@2809.85,3709.77 2828.19,3709.77 2853.52,3735.1 v1(2879.37,3735.1) ; R1R_IDL_17_12_TerA2.2@2760.89,3925.68 2766.8,3919.77 CR_IDL_17_12_TerA2.2@2809.85,3919.77 2826.14,3936.06 v1(2861.29,3936.06) ; R1R_IDL_17_12_TerA13.2@2763.59,2346.38 2762.5,2347.47 R1R_IDL_17_12_TerA13.2@2760.52,2347.47 2766.43,2341.56 CR_IDL_17_12_TerA13.2@2809.48,2341.56 2814.3,2346.38 v1(2906.5,2346.38) ; R1R_IDL_17_12_TerA3.2@2765.77,3819.66 2766.42,3820.31 v1(2860.94,3820.31) ; R1R_IDL_17_12_TerA1.2@2765.89,4036.92 2771.8,4031.01 CR_IDL_17_12_TerA1.2@2814.85,4031.01 2833.19,4031.01 2858.52,4056.34 v1(2868.37,4056.34) ; R1R_IDL_17_12_TerA15.2@2766.53,2022.53 2772.44,2016.62 CR_IDL_17_12_TerA15.2@2815.49,2016.62 2859.68,2016.62 v1(2869.01,2025.95) ; R1R_IDL_17_12_TerA23.2@2772.23,1108.82 2778.14,1102.92 CR_IDL_17_12_TerA23.2@2821.19,1102.92 2821.68,1103.41 v1(2877.23,1103.41) ; R1R_IDL_17_12_TerA22.2@2772.23,1213.82 2778.14,1207.92 CR_IDL_17_12_TerA22.2@2821.19,1207.92 2839.52,1207.92 2864.85,1233.25 v1(2890.71,1233.25) ; R1R_IDL_17_12_TerA21.2@2772.23,1318.82 2815.28,1318.82 CR_IDL_17_12_TerA21.2@2821.19,1312.92 2839.52,1312.92 2857.48,1330.87 v1(2890.91,1330.87) ; R1R_IDL_17_12_TerA20.2@2772.23,1423.82 2815.28,1423.82 CR_IDL_17_12_TerA20.2@2821.19,1417.92 2822.6,1419.33 2844.04,1419.33 2865.26,1440.56 2895.8,1440.56 v1(2917.03,1419.33) ; R1R_IDL_17_12_TerA19.2@2772.23,1528.82 2775.65,1532.25 v1(2858.71,1532.25) ; R1R_IDL_17_12_TerA18.2@2772.23,1633.82 2778.14,1627.92 CR_IDL_17_12_TerA18.2@2821.19,1627.92 2846.52,1653.25 v1(2874.71,1653.25) ; R1R_IDL_17_12_TerA17.2@2772.23,1736.44 v1(2871.28,1736.44) ; R1R_IDL_17_12_TerA16.2@2772.23,1841.82 2778.14,1835.92 CR_IDL_17_12_TerA16.2@2821.19,1835.92 2828.57,1843.3 v1(2828.57,1899.84) ; CR_IDL_17_12_TerA6.2@2817.29,3500.22 v1(2867.08,3500.22)
  other v1: 3949.95,-3612.7 3608.27,-1930.2 3955.44,-1921.61 3553.65,-1432.21 3968.21,-1416.77 3556.23,-1327.37
12V: Jtop1.C31 Jtop2.C31 Jtop3.C31 Jtop4.C31 PT5.1 PT5.2 PT5.3 PT5.4 PT5.5 PT5.6
-3V3: -3V3.1 -3V3.2 -3V3.3 -3V3.4 -3V3.5 -3V3.6 JMid1.27 JMid1.28 JMid1.46 JMid1.47 JMid1.65 JMid1.66 JMid1.83 JMid1.84 JMid1.85 JMid2.27 JMid2.28 JMid2.46 JMid2.47 JMid2.65 JMid2.66 JMid2.83 JMid2.84 JMid2.85 JMid3.27 JMid3.28 JMid3.46 JMid3.47 JMid3.65 JMid3.66 JMid3.83 JMid3.84 JMid3.85 JMid4.27 JMid4.28 JMid4.46 JMid4.47 JMid4.65 JMid4.66 JMid4.83 JMid4.84 JMid4.85
-5V: -5V.1 -5V.2 -5V.3 -5V.4 -5V.5 -5V.6 JMid1.30 JMid1.49 JMid1.68 JMid1.87 JMid2.30 JMid2.49 JMid2.68 JMid2.87 JMid3.30 JMid3.49 JMid3.68 JMid3.87 JMid4.30 JMid4.49 JMid4.68 JMid4.87
-12V: -12V.1 -12V.2 -12V.3 -12V.4 -12V.5 -12V.6 Jtop1.A31 Jtop2.A31 Jtop3.A31 Jtop4.A31
BG0IN_5: Jtop1.B4 Jtop2.B4 Jtop3.B4 Jtop4.B4 | length 2505.9
  Bot Signal w8: Jtop1.B4@128.79,1382.06 171.69,1424.96 846.32,1424.96 888.8,1382.48 Jtop2.B4@928.72,1382.48 ; Jtop2.B4@948.2,1379.26 991.1,1422.16 1665.73,1422.16 1708.21,1379.68 Jtop3.B4@1748.13,1379.68 ; Jtop3.B4@1756.8,1388.51 1799.7,1431.41 2474.33,1431.41 2516.81,1388.93 Jtop4.B4@2556.73,1388.93
BG0OUT_5: Jtop1.B5 Jtop2.B5 Jtop3.B5 Jtop4.B5 | length 2505.9
  Bot Signal w8: Jtop1.B5@128.79,1482.06 171.69,1524.96 846.32,1524.96 888.8,1482.48 Jtop2.B5@928.72,1482.48 ; Jtop2.B5@948.2,1479.26 991.1,1522.16 1665.73,1522.16 1708.21,1479.68 Jtop3.B5@1748.13,1479.68 ; Jtop3.B5@1756.8,1488.51 1799.7,1531.41 2474.33,1531.41 2516.81,1488.93 Jtop4.B5@2556.73,1488.93
BG1IN_5: Jtop1.B6 Jtop2.B6 Jtop3.B6 Jtop4.B6 | length 2505.9
  Bot Signal w8: Jtop1.B6@128.79,1582.06 171.69,1624.96 846.32,1624.96 888.8,1582.48 Jtop2.B6@928.72,1582.48 ; Jtop2.B6@948.2,1579.26 991.1,1622.16 1665.73,1622.16 1708.21,1579.68 Jtop3.B6@1748.13,1579.68 ; Jtop3.B6@1756.8,1588.51 1799.7,1631.41 2474.33,1631.41 2516.81,1588.93 Jtop4.B6@2556.73,1588.93
BG1OUT_5: Jtop1.B7 Jtop2.B7 Jtop3.B7 Jtop4.B7 | length 2505.9
  Bot Signal w8: Jtop1.B7@128.79,1682.06 171.69,1724.96 846.32,1724.96 888.8,1682.48 Jtop2.B7@928.72,1682.48 ; Jtop2.B7@948.2,1679.26 991.1,1722.16 1665.73,1722.16 1708.21,1679.68 Jtop3.B7@1748.13,1679.68 ; Jtop3.B7@1756.8,1688.51 1799.7,1731.41 2474.33,1731.41 2516.81,1688.93 Jtop4.B7@2556.73,1688.93
BG2IN_5: Jtop1.B8 Jtop2.B8 Jtop3.B8 Jtop4.B8 | length 2499.4
  Bot Signal w8: Jtop1.B8@128.79,1782.06 171.69,1824.96 846.32,1824.96 888.8,1782.48 Jtop2.B8@928.72,1782.48 ; Jtop2.B8@948.2,1779.26 991.1,1822.16 1665.73,1822.16 1708.21,1779.68 Jtop3.B8@1748.13,1779.68 ; Jtop3.B8@1756.8,1788.51 1799.7,1831.41 2474.33,1831.41 2527.84,1777.9 Jtop4.B8@2545.7,1777.9
BG2OUT_5: Jtop1.B9 Jtop2.B9 Jtop3.B9 Jtop4.B9 | length 2499
  Bot Signal w8: Jtop1.B9@128.79,1882.06 171.69,1924.96 846.32,1924.96 888.8,1882.48 Jtop2.B9@928.72,1882.48 ; Jtop2.B9@948.2,1879.26 991.1,1922.16 1665.73,1922.16 1708.21,1879.68 Jtop3.B9@1748.13,1879.68 ; Jtop3.B9@1756.8,1888.51 1799.7,1931.41 2474.33,1931.41 2528.63,1877.11 Jtop4.B9@2544.91,1877.11
BG3IN_5: Jtop1.B10 Jtop2.B10 Jtop3.B10 Jtop4.B10 | length 2505.9
  Bot Signal w8: Jtop1.B10@128.79,1982.06 171.69,2024.96 846.32,2024.96 888.8,1982.48 Jtop2.B10@928.72,1982.48 ; Jtop2.B10@948.2,1979.26 991.1,2022.16 1665.73,2022.16 1708.21,1979.68 Jtop3.B10@1748.13,1979.68 ; Jtop3.B10@1756.8,1988.51 1799.7,2031.41 2474.33,2031.41 2516.81,1988.93 Jtop4.B10@2556.73,1988.93
BG3OUT_5: Jtop1.B11 Jtop2.B11 Jtop3.B11 Jtop4.B11 | length 2505.9
  Bot Signal w8: Jtop1.B11@128.79,2082.06 171.69,2124.96 846.32,2124.96 888.8,2082.48 Jtop2.B11@928.72,2082.48 ; Jtop2.B11@948.2,2079.26 991.1,2122.16 1665.73,2122.16 1708.21,2079.68 Jtop3.B11@1748.13,2079.68 ; Jtop3.B11@1756.8,2088.51 1799.7,2131.41 2474.33,2131.41 2516.81,2088.93 Jtop4.B11@2556.73,2088.93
